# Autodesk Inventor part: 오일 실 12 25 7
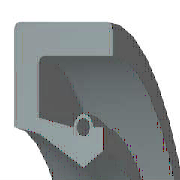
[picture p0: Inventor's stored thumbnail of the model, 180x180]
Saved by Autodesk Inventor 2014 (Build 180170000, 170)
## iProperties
IsCustomPart: 1
Created: 2012-02
Part Number: 오일 실 12 25 7
Material: 고무
Description: 오일-실
Document SubType Name: Modeling
Standard: KS B 2804
Designer: mduedu
Standards Organization: KS
Language: ko-KR
Size Designation: S - 12 25 7
Categories: <MemberInstance><Categories><Category DisplayName="샤프트 부품" InternalName="7f7aeb1f-a693-4053-b835-cee3144e0d98" Mnemonic="SHFT"><Category DisplayName="실링" Intern
Density: 0.93 g/cm^3
Appearance: 고무 - 검은색 - 버전 1.1
Mass: 1.26338 g
Surface Area: 20.8889 cm^2
Volume: 1.35847 cm^3
Author: mduedu
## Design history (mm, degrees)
revolve "본체" stored, may be unused: angle "d17" = 90 deg
revolve "스프링1" stored, may be unused: angle "d18" = 90 deg
body "Solid1"
sketch "스케치1"
  geometry: L1 (0, 12.5)-(7, 12.5); L2 (7, 12.5)-(7, 11.25); L3 (7, 11.25)-(1.75, 11.25); L4 (0, 12.5)-(0, 8.1); L5 (0, 8.1)-(1.75, 7.75); L6 (1.75, 7.75)-(4.9, 6); L7 (4.9, 6)-(0, 6); L8 (6.3, 6.875)-(6.3, 8.1); L9 (0, 0)-(9.586, 0) reference; L10 (4.9, 6)-(6.3, 6.875); L11 (0, 18)-(0, -3) reference; L12 (-1.917, 0)-(11.503, 0) reference; L13 (4.2, 8.1)-(1.75, 8.59); L14 (1.75, 8.59)-(1.75, 11.25); L15 (6.3, 8.1)-(5.6, 8.1); C1 r 0.455 at (4.9, 8.1); A1 r 0.7 centre (4.9, 8.1) between (5.6, 8.1) and (4.2, 8.1)
  constraints: 26 end point, 5 horizontal alignment, 4 perpendicular, 2 centre point, 2 collinear, 2 horizontal, 2 parallel, 2 point on circle, 2 point on line, 2 vertical alignment, 1 coincident
  dimensions: "d0" = 25 diameter of L1 L9 (= SD2); "d1" = 13.75 diameter of L8.start L9 (= ABDM); "d2" = 1.25 distance of L1.end L2.end (computed from SD); "d3" = 0.91 diameter of C1 (= SPDI); "d4" = 1.4 diameter of A1 (= SPDA); "d5" = 12 diameter of L6.end L9 (= NND); "d6" = 15.5 diameter of L5.end L9 (= TKDM); "d7" = 16.2 diameter of L4.end L9 (= HLDM); "d8" = 4.9 distance from line of C1.centre L4 (= SPDST); "d9" = 6.3 distance between parallel lines of L8 L4 (= SDI); "d10" = 7 distance between parallel lines of L2 L4 (= SWDT); "d12" = 1.75 distance between parallel lines of L14 L4 (= SD)
fillet "모깎기1" dims "d11" = 0.3 (= RR)
other parameters: "SD2" = 25 [user parameter; used in 1 equation term], "SWDT" = 7 [user parameter; used in 1 equation term], "RR" = 0.3 [user parameter; used in 1 equation term], "SD" = 1.75 [user parameter; used in 2 equation terms], "NND" = 12 [user parameter; used in 1 equation term], "SPDA" = 1.4 [user parameter; used in 1 equation term], "SPDI" = 0.91 [user parameter; used in 1 equation term], "TKDM" = 15.5 [user parameter; used in 1 equation term], "HLDM" = 16.2 [user parameter; used in 1 equation term], "ABDM" = 13.75 [user parameter; used in 1 equation term], "SDI" = 6.3 [user parameter; used in 1 equation term], "SPDST" = 4.9 [user parameter; used in 1 equation term], "d13" = 0, "d14" = 0, "d15" = 0, "LAB" = 0.35 [user parameter]
